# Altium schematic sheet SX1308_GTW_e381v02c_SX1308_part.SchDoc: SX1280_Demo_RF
size B; DrawnBy: Erik Fountain; DocumentNumber: 1; SheetNumber: 1; SheetTotal: 5; PageSetup: Record=PageOptions|CenterHorizontal=True|CenterVertical=True|PrintScale=0.72|XCorrection=1.00|YCorrection=1.00|PrintKind=0|BorderSize=5000000|LeftOffset=0|BottomOffset=0|Orientation=2|PaperLength=1000|PaperWidth=1000|Scale=100|PaperSource=7|PrintQuality=-4|MediaType=1|DitherType=10|PaperKind=Letter|PrintScaleMode=1
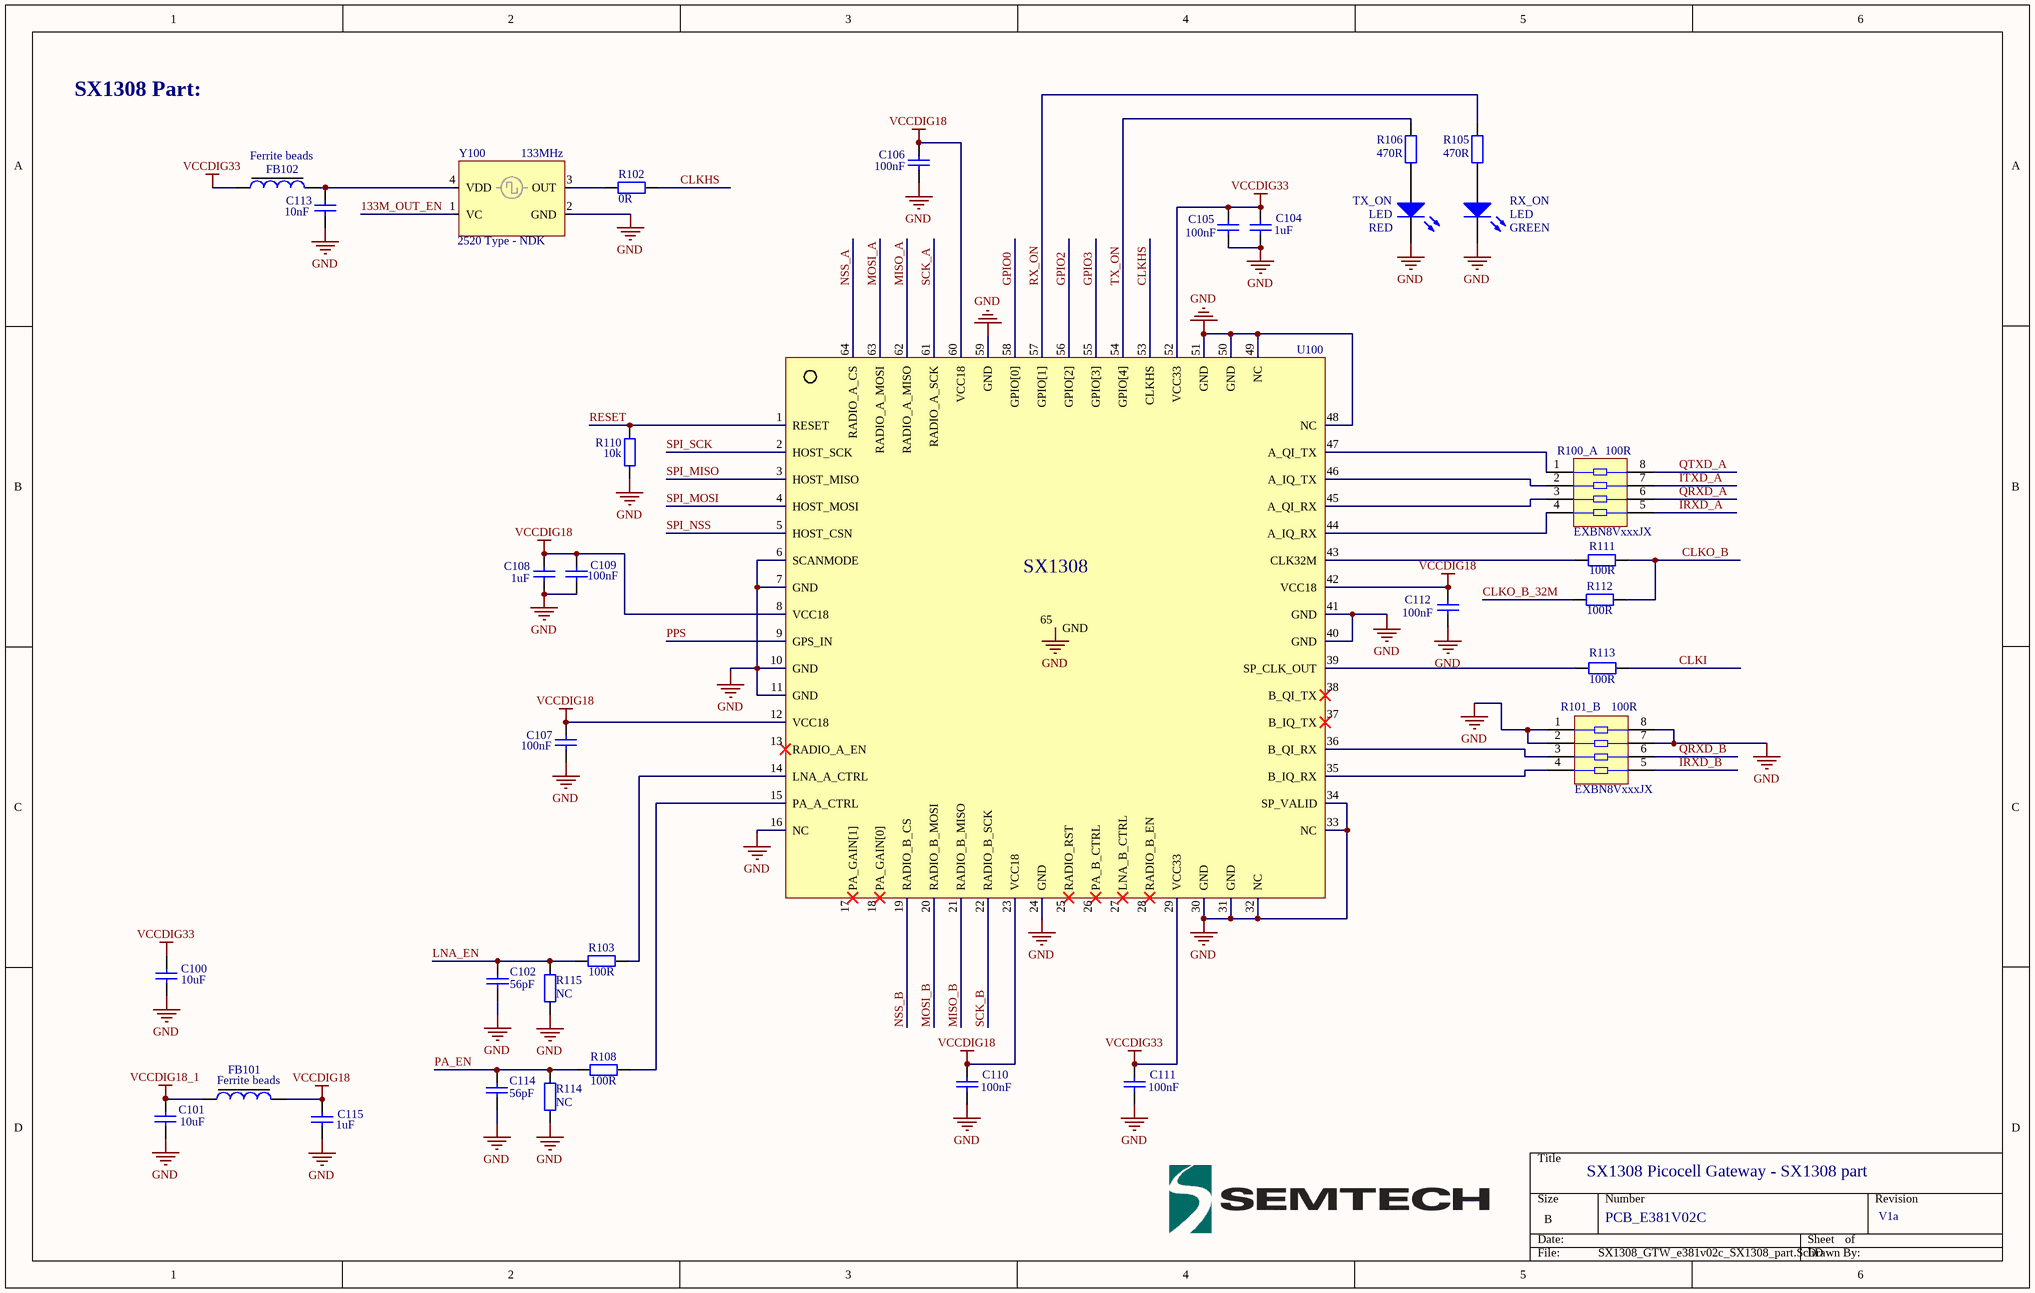
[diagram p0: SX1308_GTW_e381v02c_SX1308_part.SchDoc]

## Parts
C100  value 10uF  [rlc_805_smd]  (hidden comment: Cap)
C101  value 10uF  [rlc_805_smd]  (hidden comment: Cap)
C102  value 56pF  [rlc_402_smd]  (hidden comment: Cap)
C104  value 1uF  [rlc_603_smd]  (hidden comment: Cap)
C105  value 100nF  [rlc_402_smd]  (hidden comment: Cap)
C106  value 100nF  [rlc_402_smd]  (hidden comment: Cap)
C107  value 100nF  [rlc_402_smd]  (hidden comment: Cap)
C108  value 1uF  [rlc_603_smd]  (hidden comment: Cap)
C109  value 100nF  [rlc_402_smd]  (hidden comment: Cap)
C110  value 100nF  [rlc_402_smd]  (hidden comment: Cap)
C111  value 100nF  [rlc_402_smd]  (hidden comment: Cap)
C112  value 100nF  [rlc_402_smd]  (hidden comment: Cap)
C113  value 10nF  [rlc_402_smd]  (hidden comment: Cap)
C114  value 56pF  [rlc_402_smd]  (hidden comment: Cap)
C115  value 1uF  [rlc_603_smd]  (hidden comment: Cap)
FB101  Ferrite beads  [rlc_402_smd]
FB102  Ferrite beads  [rlc_402_smd]
R100_A  EXBN8VxxxJX  value 100R  [EXB28V]
R101_B  EXBN8VxxxJX  value 100R  [EXB28V]
R102  value 0R  [rlc_402_smd]  (hidden comment: Resistor)
R103  value 100R  [rlc_402_smd]  (hidden comment: Resistor)
R105  value 470R  [rlc_402_smd]  (hidden comment: Resistor)
R106  value 470R  [rlc_402_smd]  (hidden comment: Resistor)
R108  value 100R  [rlc_402_smd]  (hidden comment: Resistor)
R110  value 10k  [rlc_402_smd]  (hidden comment: Resistor)
R111  value 100R  [rlc_402_smd]  (hidden comment: Resistor)
R112  value 100R  [rlc_402_smd]  (hidden comment: Resistor)
R113  value 100R  [rlc_402_smd]  (hidden comment: Resistor)
R114  value NC  [rlc_402_smd]  (hidden comment: Resistor)
R115  value NC  [rlc_402_smd]  (hidden comment: Resistor)
RX_ON  LED  Type: GREEN  [CD3224]
TX_ON  LED  Type: RED  [CD3224]
U100  SX1308  [vqfn64_9x9mm]
Y100  2520 Type - NDK  value 133MHz  [TCXO 2.5x2.0mm]

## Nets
GND: C100.1 C101.1 C102.1 C104.1 C105.1 C106.1 C107.1 C108.1 C109.1 C110.1 C111.1 C112.1 C113.1 C114.1 C115.2 R101_B.1 R101_B.2 R101_B.7 R101_B.8 R110.1 R114.2 R115.2 RX_ON.2(K) TX_ON.2(K) U100.6(SCANMODE) U100.7(GND) U100.10(GND) U100.11(GND) U100.16(NC) U100.24(GND) U100.30(GND) U100.31(GND) U100.32(NC) U100.33(NC) U100.34(SP_VALID) U100.40(GND) U100.41(GND) U100.48(NC) U100.49(NC) U100.50(GND) U100.51(GND) U100.59(GND) U100.65(GND) Y100.2(GND)
VCCDIG18: C106.2 C107.2 C108.2 C109.2 C110.2 C112.2 C115.1 FB101.2 U100.8(VCC18) U100.12(VCC18) U100.23(VCC18) U100.42(VCC18) U100.60(VCC18)
VCCDIG18_1: C101.2 FB101.1
VCCDIG33: C100.2 C104.2 C105.2 C111.2 FB102.1 U100.29(VCC33) U100.52(VCC33)
133M_OUT_EN: Y100.1(VC)
CLKHS: R102.1 U100.53(CLKHS)
CLKI: R113.2
CLKO_B: R111.2 R112.2
CLKO_B_32M: R112.1
GPIO0: U100.58(GPIO[0])
GPIO2: U100.56(GPIO[2])
GPIO3: U100.55(GPIO[3])
IRXD_A: R100_A.5
IRXD_B: R101_B.5
ITXD_A: R100_A.7
LNA_EN: C102.2 R103.2 R115.1
MISO_A: U100.62(RADIO_A_MISO)
MISO_B: U100.21(RADIO_B_MISO)
MOSI_A: U100.63(RADIO_A_MOSI)
MOSI_B: U100.20(RADIO_B_MOSI)
NSS_A: U100.64(RADIO_A_CS)
NSS_B: U100.19(RADIO_B_CS)
PA_EN: C114.2 R108.2 R114.1
PPS: U100.9(GPS_IN)
QRXD_A: R100_A.6
QRXD_B: R101_B.6
QTXD_A: R100_A.8
RESET: R110.2 U100.1(RESET)
RX_ON: R105.2 U100.57(GPIO[1])
SCK_A: U100.61(RADIO_A_SCK)
SCK_B: U100.22(RADIO_B_SCK)
SPI_MISO: U100.3(HOST_MISO)
SPI_MOSI: U100.4(HOST_MOSI)
SPI_NSS: U100.5(HOST_CSN)
SPI_SCK: U100.2(HOST_SCK)
TX_ON: R106.2 U100.54(GPIO[4])
NetC113_2: C113.2 FB102.2 Y100.4(VDD)
NetR100_A_1: R100_A.1 U100.47(A_QI_TX)
NetR100_A_2: R100_A.2 U100.46(A_IQ_TX)
NetR100_A_3: R100_A.3 U100.45(A_QI_RX)
NetR100_A_4: R100_A.4 U100.44(A_IQ_RX)
NetR101_B_3: R101_B.3 U100.36(B_QI_RX)
NetR101_B_4: R101_B.4 U100.35(B_IQ_RX)
NetR102_2: R102.2 Y100.3(OUT)
NetR103_1: R103.1 U100.14(LNA_A_CTRL)
NetR105_1: R105.1 RX_ON.1(A)
NetR106_1: R106.1 TX_ON.1(A)
NetR108_1: R108.1 U100.15(PA_A_CTRL)
NetR111_1: R111.1 U100.43(CLK32M)
NetR113_1: R113.1 U100.39(SP_CLK_OUT)

Not connected (* = marked no-connect by the designer): U100 13(RADIO_A_EN)* 17(PA_GAIN[1])* 18(PA_GAIN[0])* 25(RADIO_RST)* 26(PA_B_CTRL)* 27(LNA_B_CTRL)* 28(RADIO_B_EN)* 37(B_IQ_TX)* 38(B_QI_TX)*

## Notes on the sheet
- SX1308 Part:
- SX1308 Picocell Gateway - SX1308 part
- PCB_E381V02C
- V1a

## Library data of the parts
C100-C102 C104-C115 = Cap: Capacitor SMD
FB101 FB102 = Ferrite beads: Value: VAL?
R100_A R101_B = EXBN8VxxxJX: Mini-Flat Package, Isolated Resistor Network, 0.031 W/resistor
R102 R103 R105 R106 R108 R110-R115 = Resistor: Resistor SMD - IEC symbol version
U100 = SX1301: SX1301 - Base Band Processor for Data Concentrator for Long Range Communication Network; Apps Pinout
Y100 = VCTCXO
